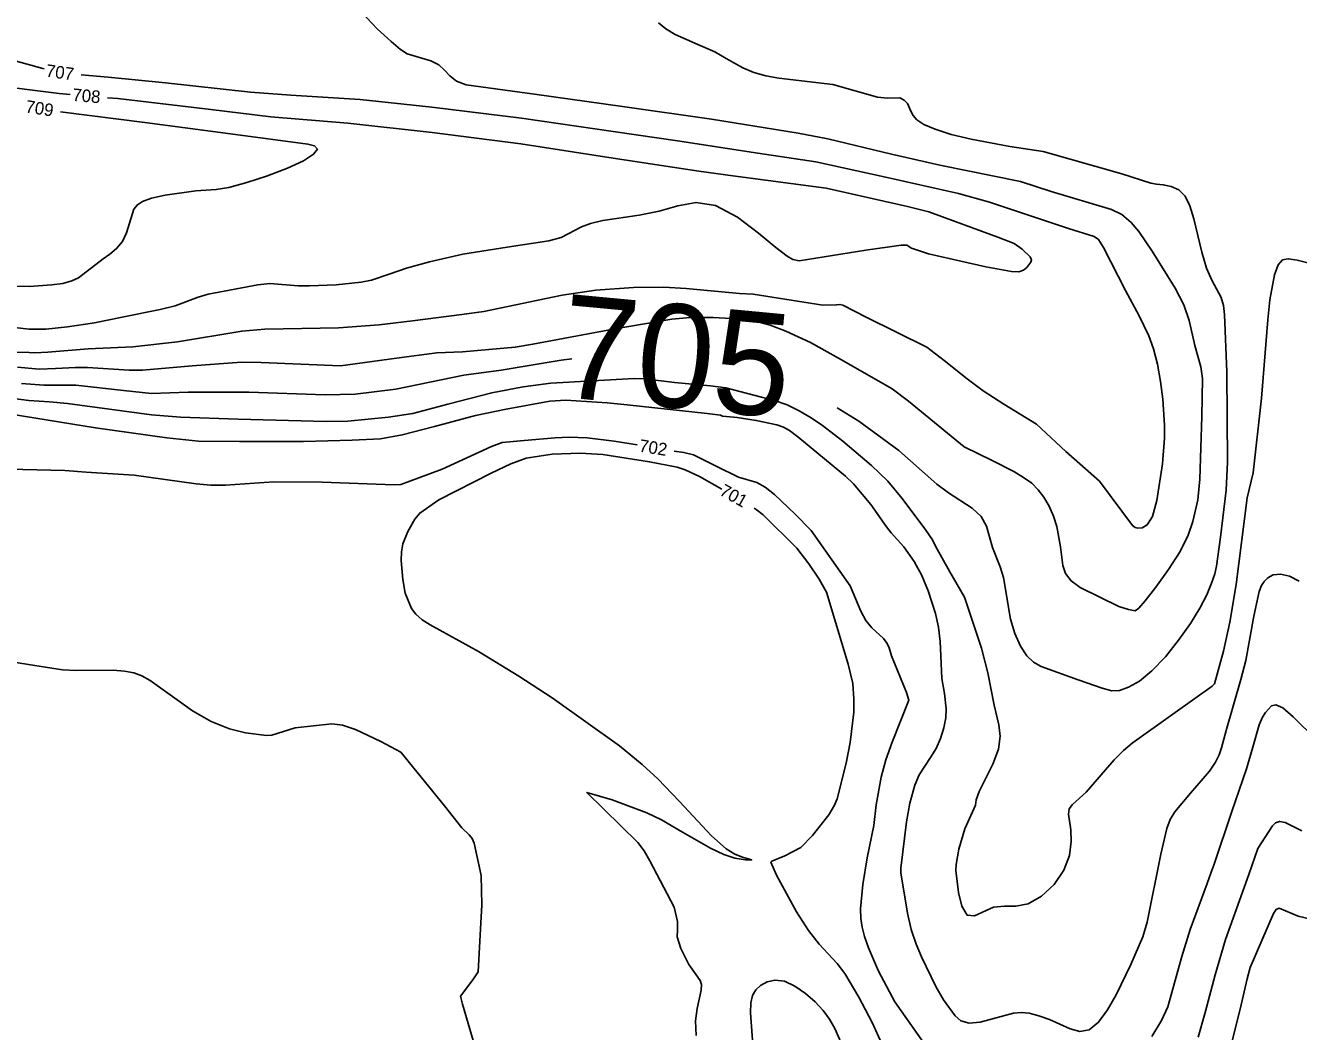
# Model space of a CAD drawing. Extents: x -291892836 to 2945206, y -477993085 to 1832792.
# Drawn here: x 1850120.5 to 1850526.8, y 544308.6 to 544629.9 of the extents above; entities that cross this region are included whole.
import ezdxf

# ---------------------------------------------------------------- set-up
doc = ezdxf.new("R2010")
doc.units = 0
doc.layers.add('DT_X_Contour_Minor', color=7, linetype='Continuous')
doc.layers.add('Level 19', color=7, linetype='Continuous')

msp = doc.modelspace()

# ---------------------------------------------------------------- linework, layer by layer
at = {"layer": 'DT_X_Contour_Minor'}
for points in [[(1850491.59, 544467.08), (1850493.15, 544471.51), (1850494.7, 544478.45), (1850495.39, 544485.05), (1850496.02, 544505.02), (1850496.21, 544517.09), (1850495.67, 544520.88), (1850493.74, 544527.69), (1850491.99, 544535.7), (1850490.22, 544540.67), (1850487.51, 544546), (1850480.09, 544557.76), (1850475.87, 544564.05), (1850473.43, 544566.95), (1850470.5, 544569.46), (1850467.15, 544571.12), (1850447.9, 544576.88), (1850438.12, 544580.08), (1850412.38, 544585.28), (1850396.93, 544588.76), (1850376.58, 544593.7), (1850367.11, 544595.47), (1850339.47, 544599.93), (1850311.07, 544604.03), (1850282.98, 544607.89), (1850261.18, 544610.91), (1850258.06, 544612.05), (1850255.93, 544613.72), (1850254.31, 544615.6), (1850252.48, 544617.31), (1850249.94, 544618.53), (1850242.37, 544620.79), (1850240.28, 544622.14), (1850237.24, 544624.69), (1850232.78, 544628.78), (1850228.05, 544633.9)], [(1850322.53, 544630.66), (1850324.88, 544628.8), (1850327.88, 544626.98), (1850335.15, 544623.75), (1850340.59, 544621.44), (1850344.16, 544619.35), (1850349.52, 544616.27), (1850353, 544614.83), (1850356.87, 544613.77), (1850360.98, 544613.06), (1850378.17, 544610.96), (1850392.52, 544606.99), (1850395.71, 544606.68), (1850399.65, 544606.7), (1850401.02, 544606.02), (1850402.1, 544604.89), (1850403.27, 544602.32), (1850403.83, 544601.07), (1850405.02, 544599.74), (1850407.31, 544598.26), (1850410.91, 544596.69), (1850415.97, 544595.09), (1850422.39, 544593.55), (1850434.7, 544591.24), (1850445.34, 544589.64), (1850470.42, 544582.45), (1850479.72, 544579.48), (1850481.56, 544579.17), (1850483.65, 544578.98), (1850486.22, 544578.48), (1850488.69, 544577.37), (1850490.63, 544575.35), (1850492.12, 544572.3), (1850493.39, 544568.15), (1850495.95, 544557.43), (1850497.45, 544552.41), (1850499.15, 544548.53), (1850502.13, 544543.02), (1850502.9, 544540.46), (1850503.27, 544537.52), (1850504.01, 544519.26), (1850504.19, 544490.44), (1850503.73, 544481.45), (1850501.92, 544466.43), (1850500.69, 544457.25), (1850500.11, 544454.79), (1850499.12, 544451.77), (1850497.56, 544448.11), (1850495.32, 544443.81), (1850492.32, 544438.91), (1850488.55, 544433.55), (1850484.34, 544428.28), (1850480.08, 544423.77), (1850476.13, 544420.54), (1850472.63, 544418.54), (1850469.66, 544417.57), (1850467.27, 544417.42), (1850464.2, 544418.22), (1850456.55, 544420.97), (1850444.76, 544425.19), (1850442.22, 544426.52), (1850440.08, 544428.56), (1850438.07, 544431.71), (1850436.29, 544435.75), (1850434.93, 544440.31), (1850432.68, 544453.6), (1850431.57, 544457.01), (1850429.14, 544463.13), (1850427.27, 544469.95), (1850425.53, 544473.12), (1850422.65, 544475.77), (1850415.11, 544480.63), (1850411.46, 544483.45), (1850399.3, 544494.17), (1850386.5, 544503.52), (1850379.62, 544507.82)], [(1850126.47, 544615.99), (1850126.07, 544616.08), (1850117.25, 544618.6)], [(1850463.31, 544484.41), (1850473.83, 544470.18), (1850474.68, 544469.53), (1850475.55, 544469.4), (1850476.9, 544469.46), (1850478.55, 544470.39), (1850480.21, 544473.12), (1850481.62, 544478.15), (1850483.46, 544489.92), (1850484.11, 544498.11), (1850484.11, 544502.27), (1850483.52, 544510.53), (1850482.83, 544516.14), (1850481.85, 544521.72), (1850480.55, 544526.6), (1850479.06, 544530.73), (1850475.98, 544537.14), (1850471.61, 544545.23), (1850464.63, 544558.95), (1850463, 544561.48), (1850461.59, 544562.46), (1850453.4, 544565.02), (1850428.26, 544573.47), (1850418.37, 544576.23), (1850394.58, 544581.48), (1850372.74, 544586.36), (1850354.32, 544589.04), (1850328.61, 544592.98), (1850302.21, 544596.88), (1850278.85, 544600.23), (1850250.25, 544603.74), (1850227.37, 544606.17), (1850205.23, 544607.62), (1850192.36, 544608.54), (1850165.2, 544611.5), (1850146.92, 544613.33), (1850138.31, 544614.05)], [(1850108.27, 544610.95), (1850131.25, 544608.16), (1850134.82, 544607.85)], [(1850146.77, 544606.79), (1850149.97, 544606.51), (1850179.73, 544603.07), (1850198.82, 544600.7), (1850223.39, 544598.62), (1850250.36, 544595.65), (1850278.65, 544592.03), (1850308.13, 544587.46), (1850335.5, 544583.37), (1850346.32, 544581.88), (1850376.09, 544577.93), (1850402.08, 544572.05), (1850408.88, 544570.31), (1850430.86, 544562.24), (1850436.04, 544560.23), (1850438.6, 544558.48), (1850441.24, 544556), (1850441.62, 544555.05), (1850441.38, 544554.26), (1850440.1, 544552.54), (1850439.09, 544551.7), (1850437.56, 544551.21), (1850435.26, 544551.27), (1850427.1, 544552.84), (1850408.75, 544556.9), (1850403.36, 544558.77), (1850401.79, 544559.7), (1850400.05, 544559.7), (1850388.74, 544558.12), (1850367.49, 544554.69)], [(1850115.26, 544546.6), (1850121.77, 544546.51), (1850128.91, 544547), (1850132.42, 544547.51), (1850135.37, 544548.27), (1850137.47, 544549.3), (1850145.36, 544555.32), (1850147.49, 544556.8), (1850149.61, 544558.61), (1850151.46, 544560.87), (1850152.83, 544563.61), (1850154.66, 544569.82), (1850155.13, 544571.19), (1850156.28, 544572.63), (1850157.87, 544573.64), (1850160.76, 544574.7), (1850165.17, 544575.7), (1850174.88, 544577.02), (1850181.41, 544577.43), (1850185.4, 544578.16), (1850191.14, 544579.71), (1850197.81, 544581.87), (1850204.2, 544584.28), (1850209.25, 544586.64), (1850212.52, 544588.72), (1850213.73, 544590.34), (1850212.83, 544591.38), (1850210.69, 544591.96), (1850184.43, 544595.47), (1850158.62, 544598.89), (1850131.77, 544602.32)], [(1850367.49, 544554.69), (1850365.5, 544555.15), (1850363.6, 544556.22), (1850360.06, 544558.91), (1850354.51, 544563.55), (1850347.74, 544568.69), (1850340.82, 544572.4), (1850334.56, 544573.34), (1850328.72, 544572.28), (1850322.78, 544570.58), (1850316.42, 544569.29), (1850304.82, 544567.57), (1850300.84, 544566.6), (1850298.02, 544565.51), (1850291.55, 544562.15), (1850287.58, 544561.11), (1850274.26, 544559.09), (1850260.11, 544556.79), (1850249.48, 544554.38), (1850242.11, 544552.41), (1850236.59, 544550.43), (1850231.02, 544548.55), (1850227.63, 544547.9), (1850219.69, 544547.09), (1850211.22, 544546.68), (1850207.54, 544546.75), (1850198.58, 544547.43), (1850194.69, 544546.99), (1850178.84, 544544.1), (1850175.62, 544543.14), (1850168.34, 544540.39), (1850163.48, 544539.18), (1850151.42, 544536.72), (1850142.54, 544534.9), (1850133.92, 544533.6), (1850127.03, 544532.9), (1850121.67, 544532.89), (1850105.79, 544534.74)], [(1850534.53, 544552.85), (1850526.37, 544554.89), (1850523.59, 544555.36), (1850521.68, 544555), (1850520.32, 544553.38), (1850519.22, 544550.26), (1850517.71, 544542.29), (1850517.01, 544535.83), (1850514.99, 544510.83), (1850512.39, 544487), (1850510.42, 544479.05), (1850506.97, 544451.36), (1850504.95, 544439.34), (1850502.91, 544430.12), (1850500.03, 544419.63), (1850499.28, 544418.9), (1850486.77, 544409.92), (1850473.71, 544400.69), (1850470.98, 544398.33), (1850467.98, 544395.34), (1850459.02, 544385.1), (1850454.69, 544381.16), (1850453.6, 544379.7), (1850453.38, 544378.07), (1850454.16, 544373.09), (1850454.29, 544369.3), (1850453.7, 544364.87), (1850451.96, 544360.18), (1850448.86, 544355.64), (1850444.86, 544351.85), (1850440.6, 544349.41), (1850436.62, 544348.66), (1850432.96, 544348.71), (1850429.54, 544348.39), (1850423.43, 544345.61), (1850421.09, 544345.84), (1850419.42, 544348.7), (1850418.35, 544353.06), (1850417.5, 544360.07), (1850417.56, 544362.01), (1850418.48, 544366.87), (1850420.34, 544373.33), (1850423.7, 544380.9), (1850423.95, 544382.58), (1850424.87, 544385.23), (1850429.26, 544394.01), (1850431.06, 544398.81), (1850431.59, 544402.97), (1850431.16, 544406.56), (1850429.72, 544412.82), (1850427.73, 544423.19), (1850425.7, 544431.05), (1850420.21, 544447.28), (1850415.57, 544455.45), (1850411, 544463.58), (1850410.02, 544465.6), (1850407.89, 544468.7), (1850400.38, 544478.84), (1850395.72, 544484.4), (1850390.6, 544489.36), (1850381.43, 544497.16), (1850374.9, 544502.18), (1850371.29, 544504.61)], [(1850112.66, 544525.64), (1850121.67, 544525.42), (1850123.55, 544525.28), (1850127.71, 544525.57), (1850140.57, 544526.65), (1850154.81, 544527.28), (1850169.11, 544528.88), (1850189.57, 544532.3), (1850196.91, 544532.87), (1850220.48, 544533.26), (1850233.4, 544534.24), (1850244.07, 544535.59), (1850259.82, 544537.59), (1850266.79, 544538.57), (1850291.83, 544543.7), (1850302.57, 544545.33), (1850314.6, 544546.14), (1850324.29, 544546.28), (1850331.44, 544545.84), (1850348.44, 544544.26), (1850352.84, 544544.04), (1850362.94, 544542.47), (1850375.05, 544540.53), (1850379.32, 544540.61), (1850380.46, 544540.81), (1850381.44, 544540.53), (1850388.81, 544536.7), (1850408.19, 544527.19), (1850413.79, 544522.91), (1850421.05, 544516.98), (1850426.2, 544513.19), (1850432.78, 544508.91), (1850443.24, 544502.52), (1850452.55, 544493.86), (1850463.31, 544484.41)], [(1850118.05, 544520.79), (1850124.96, 544520.14), (1850130.11, 544520.29), (1850136.5, 544520.68), (1850140.35, 544520.67), (1850153.68, 544519.79), (1850157.9, 544519.85), (1850173.79, 544521.19), (1850189.46, 544522.35), (1850195.72, 544522.26), (1850221.09, 544521.14), (1850238.99, 544523.63), (1850251.83, 544525.29), (1850259.99, 544525.68), (1850276.85, 544527.1), (1850282.47, 544528.08), (1850308.08, 544532.87), (1850326.84, 544536.05), (1850332.67, 544536.56), (1850340.17, 544536.56), (1850349.34, 544536.13), (1850353.45, 544535.49), (1850358.21, 544534.13), (1850363.23, 544532.24), (1850371.07, 544528.62), (1850380.98, 544523.13), (1850397.18, 544513.82), (1850402.33, 544509.85), (1850420.16, 544495.3), (1850429.04, 544490.98), (1850436.03, 544487.42), (1850439.11, 544485.57), (1850441.68, 544483.68), (1850443.79, 544481.62), (1850445.61, 544479.22), (1850447.22, 544476.35), (1850448.6, 544473.16), (1850449.69, 544469.84), (1850450.93, 544463.35), (1850451.65, 544457.47), (1850452.48, 544454.87), (1850454.24, 544452.51), (1850457.2, 544450.43), (1850469.46, 544444.36), (1850472.54, 544443.35), (1850474.73, 544443.01), (1850475.86, 544443.82), (1850477.91, 544446.18), (1850481.31, 544450.52), (1850485.36, 544456.11), (1850489.04, 544461.91), (1850491.59, 544467.08)], [(1850294.93, 544523.46), (1850291.54, 544522.98), (1850272.32, 544519.77), (1850260.43, 544518.15), (1850238.71, 544513.68), (1850225.74, 544512.18), (1850216.19, 544511.91), (1850191.88, 544512.81), (1850172.47, 544512.82), (1850160.75, 544512.4), (1850151.82, 544513.32), (1850136.67, 544515), (1850132.51, 544515.01), (1850126.37, 544514.99), (1850119.24, 544515.58)], [(1850371.29, 544504.61), (1850367.52, 544506.84), (1850363.69, 544508.69), (1850359.92, 544510.04), (1850344.08, 544514.16), (1850339.13, 544514.79), (1850327.66, 544515.84), (1850318.18, 544517.08), (1850314.79, 544517.13), (1850288.2, 544515.64), (1850279.42, 544514.43), (1850269.35, 544512.58), (1850255.39, 544508.93), (1850244.17, 544505.99), (1850236.38, 544504.81), (1850223.45, 544503.47), (1850216.47, 544503.42), (1850188.4, 544504.18), (1850170.02, 544504.76), (1850160.79, 544505.58), (1850133.98, 544509.18), (1850128.22, 544509.64), (1850121.65, 544510.09), (1850105.21, 544512.21)], [(1850390.35, 544476.93), (1850384.79, 544483.54), (1850382.25, 544486), (1850367, 544498.51), (1850364.34, 544500.57), (1850362.47, 544501.65), (1850360.38, 544502.33), (1850353.75, 544503.75), (1850347.67, 544504.64), (1850343.02, 544505.16), (1850342.35, 544505.43), (1850338.15, 544505.91), (1850312.54, 544508.68), (1850306.2, 544509.36), (1850293, 544510.18), (1850287.92, 544509.94), (1850274.01, 544507.39), (1850264.14, 544505.33), (1850251.08, 544501.83), (1850240.77, 544499.14), (1850233.87, 544497.92), (1850224.78, 544497.42), (1850209.25, 544497.06), (1850188.9, 544496.99), (1850175.73, 544497.09), (1850165.66, 544498.22), (1850142.93, 544501.35), (1850115.94, 544505.73)], [(1850315.73, 544495.93), (1850308.42, 544497.11), (1850299.8, 544498.23), (1850294.04, 544498.43), (1850289.61, 544498.22), (1850279.72, 544497.29), (1850272.67, 544496.73), (1850269.26, 544495.47), (1850253.55, 544488.21), (1850246.13, 544485.43), (1850240.35, 544483.25), (1850238.17, 544483.2), (1850215.26, 544484.09), (1850199.79, 544484.1), (1850184.36, 544483.04), (1850179.65, 544483.09), (1850175.04, 544483.51), (1850155.23, 544486.28), (1850139.92, 544487.18), (1850133.09, 544487.79), (1850106.23, 544488.44)], [(1850342.82, 544481.84), (1850335.69, 544485.84), (1850331.06, 544487.99), (1850328.49, 544488.84), (1850319.73, 544490.55), (1850304.82, 544492.82), (1850297.53, 544493.34), (1850288.62, 544493.03), (1850280.35, 544491.66), (1850275.46, 544489.91), (1850269.21, 544486.89), (1850252.46, 544478.41), (1850246.4, 544474.18), (1850244.83, 544472.19), (1850242.61, 544468.24), (1850240.98, 544464.39), (1850240.55, 544461.81), (1850240.43, 544459.05), (1850240.99, 544452.99), (1850241.77, 544448.59), (1850243.78, 544443.7), (1850245.13, 544441.93), (1850247.14, 544440.12), (1850249.68, 544438.44), (1850265.09, 544430.03), (1850277.97, 544422.09), (1850288.59, 544415.18), (1850310.11, 544399.86), (1850317.37, 544393.93), (1850322.34, 544389.36), (1850329.23, 544382.12), (1850339.54, 544371.13), (1850344.14, 544366.96), (1850346.96, 544365.25), (1850349.38, 544364.28), (1850352.35, 544363.42), (1850350.32, 544363.5), (1850346.92, 544364.03), (1850343.38, 544365.17), (1850339.18, 544367.23), (1850330.24, 544372.31), (1850323.53, 544376.24), (1850318.88, 544378.47), (1850307.75, 544382.6), (1850299.74, 544384.99), (1850316.01, 544368.96), (1850317.96, 544366.37), (1850319.84, 544363.15), (1850327.59, 544348.31), (1850328.62, 544343.77), (1850328.63, 544341.16), (1850328.53, 544338.84), (1850329.73, 544335.14), (1850332.25, 544330.01), (1850334.56, 544326.79), (1850335.91, 544324.91), (1850336.29, 544323.64), (1850336.23, 544321.84), (1850334.87, 544316.04), (1850334.41, 544312.03), (1850334.59, 544307.41)], [(1850409.43, 544301.91), (1850398.04, 544318.13), (1850392.82, 544327.97), (1850389.62, 544335.37), (1850388.35, 544338.94), (1850387.54, 544341.97), (1850387.15, 544344.76), (1850387.1, 544347.81), (1850387.75, 544355.57), (1850389.19, 544364.07), (1850391.26, 544374.41), (1850392.04, 544381.05), (1850393.67, 544389.82), (1850395.14, 544395.34), (1850397.11, 544401.08), (1850402.47, 544414.41), (1850401.71, 544416.85), (1850396.89, 544428.57), (1850396.18, 544431.11), (1850395.51, 544432.57), (1850394.38, 544434.09), (1850390.68, 544437.51), (1850388.74, 544439.87), (1850387.16, 544442.88), (1850383.75, 544450.89), (1850371.32, 544468.62), (1850366.24, 544473.84), (1850359.56, 544480.09), (1850356.65, 544482.43), (1850353.91, 544483.95), (1850348.16, 544485.64), (1850341.22, 544489.07), (1850333.76, 544492.75), (1850330.61, 544493.5), (1850327.58, 544493.99)], [(1850393.88, 544304.7), (1850390.72, 544311.54), (1850386.51, 544319.67), (1850382.05, 544327.19), (1850379.6, 544330.41), (1850373.84, 544336.53), (1850370.4, 544340.92), (1850366.63, 544346.9), (1850360.28, 544358.54), (1850358.44, 544362.69), (1850358.73, 544363.01), (1850362.88, 544364.71), (1850367.96, 544367.39), (1850371.72, 544371.21), (1850376.96, 544377.88), (1850378.74, 544380.87), (1850379.58, 544382.93), (1850382.45, 544394.33), (1850383.76, 544400.92), (1850384.9, 544410.61), (1850384.93, 544414.82), (1850384.55, 544419.71), (1850383.13, 544425.89), (1850376.24, 544448.92), (1850373.86, 544453.09), (1850370.56, 544458), (1850366.76, 544462.92), (1850355.95, 544473.59), (1850353.79, 544475.26), (1850353.13, 544475.69)], [(1850527.07, 544452.45), (1850523.97, 544454.04), (1850521.08, 544454.72), (1850518.8, 544454.46), (1850517.1, 544453.54), (1850515.88, 544452.33), (1850514.98, 544451.02), (1850514.24, 544449.12), (1850512.6, 544441.28), (1850510.01, 544427.14), (1850508.38, 544421), (1850503.8, 544404.8), (1850502.31, 544399.26), (1850501.51, 544396.98), (1850500.32, 544394.62), (1850498.39, 544391.82), (1850492.33, 544384.7), (1850487.33, 544378.74), (1850485.91, 544376.33), (1850484.83, 544373.46), (1850482.89, 544365.25), (1850478.52, 544343.61), (1850477.11, 544338.83), (1850473.3, 544330), (1850468.61, 544320.31), (1850465.87, 544315.56), (1850462.98, 544311.65), (1850460.02, 544309.23), (1850457.05, 544308.69), (1850454.01, 544309.54), (1850447.37, 544312.5), (1850443.98, 544313.71), (1850440.92, 544314.51), (1850438.34, 544314.75), (1850435.84, 544314.47), (1850425.23, 544311.59), (1850421.7, 544311.3), (1850419.11, 544312.09), (1850417.31, 544313.63), (1850413.52, 544318.79), (1850411.06, 544323.05), (1850406.5, 544332.51), (1850404.8, 544336.53), (1850403.26, 544341.2), (1850402.01, 544346.48), (1850399.93, 544359.31), (1850399.95, 544360.78), (1850401.7, 544375.63), (1850402.75, 544381.54), (1850404.38, 544387.34), (1850405.73, 544390.55), (1850409.38, 544396.14), (1850411.17, 544399), (1850412.63, 544402.21), (1850413.66, 544405.57), (1850414.26, 544408.79), (1850414.41, 544411.64), (1850413.87, 544416.53), (1850413.05, 544421.4), (1850412.65, 544428.59), (1850412.47, 544433.12), (1850411.98, 544437.76), (1850411.03, 544442.13), (1850408.59, 544449.32), (1850406.62, 544454.2), (1850404.13, 544458.75), (1850400.86, 544463.41), (1850396.85, 544467.85), (1850395.31, 544469.79), (1850390.35, 544476.93)], [(1850116.18, 544426.66), (1850123.5, 544425.55), (1850132.4, 544424.14), (1850136.7, 544423.92), (1850148.57, 544424.02), (1850152.11, 544423.74), (1850155.18, 544423.18), (1850157.72, 544422.24), (1850160.32, 544420.69), (1850173.84, 544411.01), (1850179.79, 544407.64), (1850185.61, 544405.33), (1850190.8, 544403.99), (1850197.49, 544403.15), (1850199.19, 544403.31), (1850206.59, 544405.62), (1850218.37, 544406.91), (1850221.68, 544406.48), (1850225.88, 544405.04), (1850234.01, 544401.23), (1850240.37, 544397.82), (1850254.24, 544380.73), (1850259.82, 544373.66), (1850262.13, 544371.49), (1850263.11, 544370.24), (1850263.71, 544368.83), (1850266.01, 544358.44), (1850266.2, 544349.13), (1850265.6, 544337.46), (1850265, 544327.72), (1850263.37, 544325.2), (1850259.36, 544319.9), (1850260.01, 544317.37)], [(1850532.59, 544401.81), (1850525.13, 544409.15), (1850521.86, 544411.94), (1850519.64, 544412.99), (1850518.23, 544412.68), (1850516.28, 544410.53), (1850515.31, 544408.96), (1850514.32, 544406.61), (1850512.27, 544399.42), (1850510.26, 544392.51), (1850505.58, 544378.92), (1850499.93, 544362.1), (1850498.99, 544359.51), (1850497.72, 544355.93), (1850492.3, 544341.25), (1850489.65, 544332.59), (1850485.1, 544316.58), (1850483.08, 544312.17), (1850480.03, 544307.04)], [(1850527.94, 544372.75), (1850522.57, 544375.36), (1850520.79, 544375.75), (1850519.49, 544375.32), (1850518.5, 544374.29), (1850513.9, 544367.12), (1850510.98, 544358.74), (1850503.5, 544338.06), (1850500.19, 544326.76), (1850497.01, 544314.68), (1850494.86, 544306.8)], [(1850538.37, 544342.69), (1850526.77, 544345.46), (1850520.63, 544348.07), (1850519.69, 544347.65), (1850518.88, 544346.32), (1850511.45, 544329.05), (1850510.49, 544325.48), (1850508.56, 544317.21), (1850501.32, 544288.03)], [(1850381.95, 544302.63), (1850378.88, 544309.57), (1850377.11, 544312.63), (1850375.08, 544315.41), (1850372.58, 544318.11), (1850369.49, 544320.82), (1850366.09, 544323.18), (1850362.75, 544324.71), (1850359.76, 544325.06), (1850357.22, 544324.47), (1850355.16, 544323.34), (1850353.61, 544321.94), (1850352.58, 544320.16), (1850352.05, 544317.76), (1850351.98, 544314.64), (1850353.56, 544292.91)], [(1850260.01, 544317.37), (1850264.74, 544301.44)]]:
    msp.add_lwpolyline(points, dxfattribs=at)

# ---------------------------------------------------------------- texts
at = {"layer": 'Level 19'}
for s, height, rotation, p in [('707', 4, 351.9794, (1850126.87, 544613.54)), ('708', 4, 354.9474, (1850135.4, 544605.79)), ('709', 4, 350.9481, (1850120.33, 544602.12)), ('705', 33, 354.6322, (1850289.96, 544511.36)), ('702', 4, 350.7934, (1850316.18, 544493.83)), ('701', 4, 330.7055, (1850341.72, 544480.17))]:
    msp.add_text(s, height=height, rotation=rotation, dxfattribs=at).set_placement(p)

doc.saveas('drawing.dxf')
